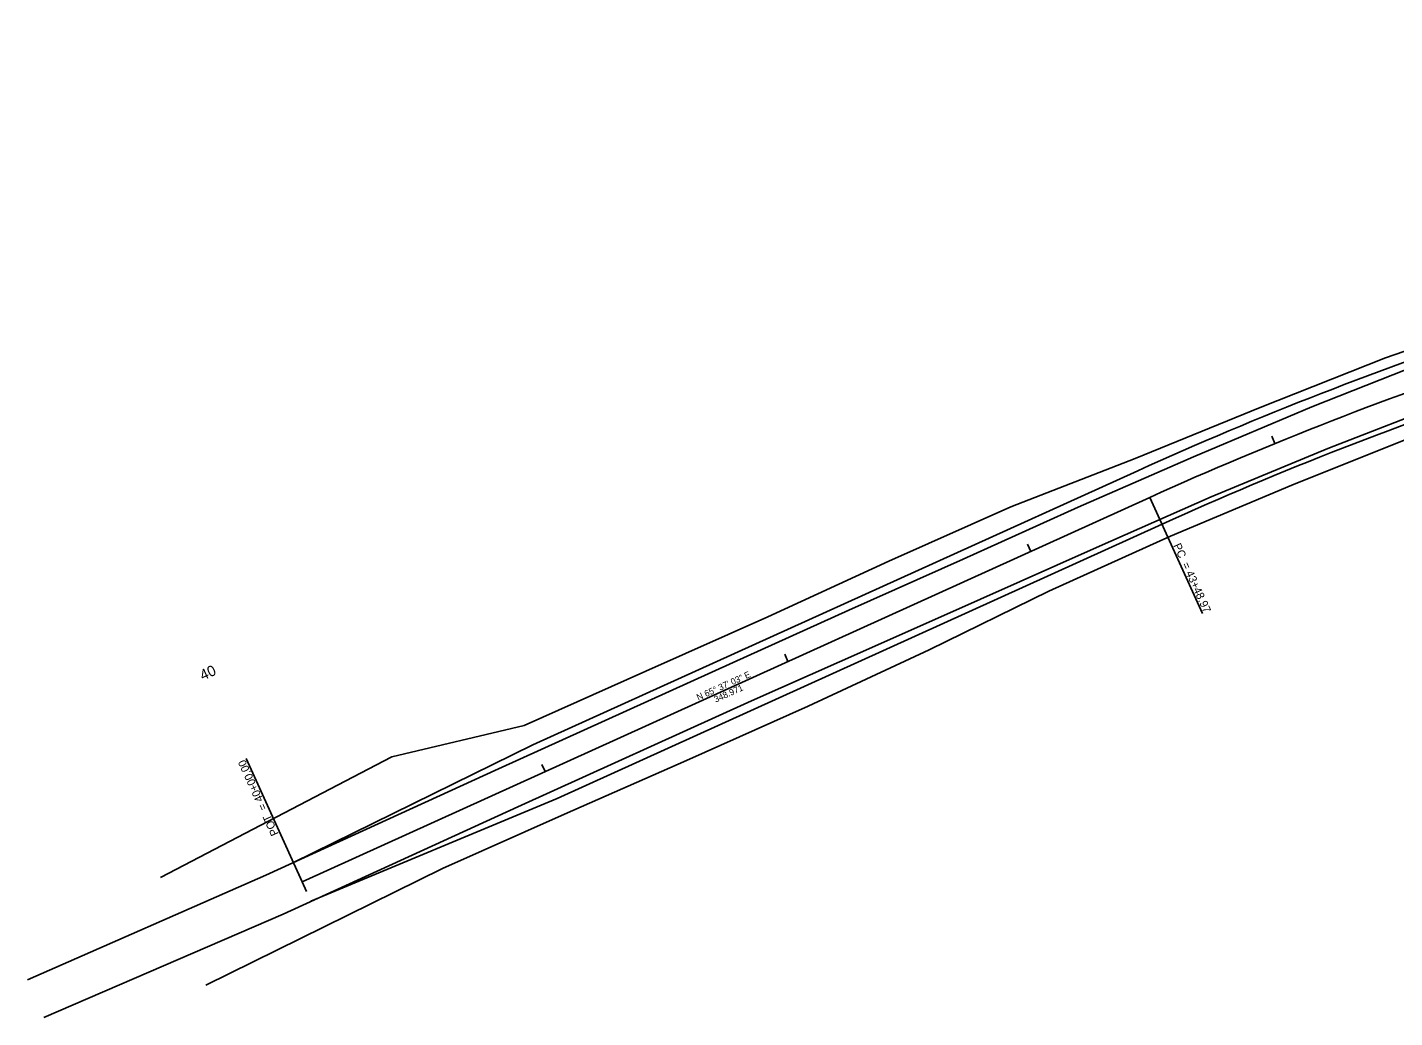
# Model space of a CAD drawing. Extents: x 1965724 to 1970316, y 1117080 to 1118173.
# Drawn here: x 1965724 to 1966236, y 1117080 to 1117451 of the extents above; entities that cross this region are included whole.
import ezdxf

# ---------------------------------------------------------------- set-up
doc = ezdxf.new("R2010")
doc.units = 0
for name, color, linetype in [('RD_EX_Road', 7, 'Continuous'), ('RD_EX_RW', 7, 'Continuous'), ('RD_HC_CL', 7, 'Continuous'), ('RD_HC_Data', 7, 'Continuous'), ('RD_HC_TX_Sta20', 7, 'Continuous'), ('RD_PD_Final_TrvlWay', 7, 'Continuous')]:
    doc.layers.add(name, color=color, linetype=linetype)

msp = doc.modelspace()

# ---------------------------------------------------------------- linework, layer by layer
at = {"layer": 'RD_EX_Road'}
for points in [[(1965723.84, 1117094.48), (1965813.3, 1117133.71), (1965900.46, 1117173.51), (1965988.47, 1117213.41), (1966031.82, 1117232.96), (1966074.66, 1117252.15), (1966117.78, 1117271.58), (1966161.06, 1117290.48), (1966205.41, 1117309.23), (1966251.25, 1117327.39), (1966297.25, 1117343.1), (1966344.08, 1117357.04), (1966390.78, 1117368.56), (1966438.12, 1117379.08), (1966484.55, 1117389.13), (1966531.2, 1117398.73), (1966578.39, 1117408.59), (1966604.53, 1117414.06), (1966624.54, 1117418.32), (1966671.32, 1117428.35), (1966716.51, 1117439.32), (1966736.6, 1117445.59), (1966754.13, 1117451.44)], [(1965729.99, 1117080.3), (1965819.77, 1117119.13), (1965907.74, 1117159.31), (1965995.36, 1117199.04), (1966039.27, 1117218.5), (1966081.24, 1117237.15), (1966124.67, 1117256.55), (1966167.66, 1117275.55), (1966211.47, 1117293.63), (1966257.79, 1117311.58), (1966302.7, 1117327.21), (1966347.9, 1117339.98), (1966394.81, 1117351.64), (1966441.56, 1117361.87), (1966488.62, 1117372.06), (1966534.91, 1117381.34), (1966581.23, 1117390.95), (1966629.53, 1117400.95), (1966675.63, 1117411.11), (1966721.68, 1117422.85), (1966766.8, 1117438.97), (1966775.75, 1117440.57)]]:
    msp.add_lwpolyline(points, dxfattribs=at)
at = {"layer": 'RD_EX_RW'}
for points in [[(1965790.81, 1117092.42), (1965879.47, 1117136.24), (1965925.17, 1117156.52), (1965970.94, 1117176.66), (1966016.61, 1117197.02), (1966061.92, 1117218.16), (1966106.86, 1117240.14), (1966152.39, 1117260.77), (1966197.92, 1117279.91), (1966243.77, 1117298.28), (1966290.04, 1117315.7), (1966337.21, 1117330.57), (1966385.03, 1117343.22), (1966433.37, 1117353.95), (1966482.26, 1117364.43), (1966531.37, 1117373.89), (1966580.17, 1117384.77), (1966628.88, 1117396.12), (1966677.82, 1117406.34), (1966728, 1117416.5), (1966777.64, 1117431.05)], [(1966139.22, 1117289.89), (1966186.05, 1117308.94), (1966233.02, 1117327.61), (1966280.8, 1117344.12), (1966329.24, 1117358.54), (1966377.84, 1117372.53)], [(1965773.8, 1117132.83), (1965860.52, 1117178.05), (1965910.11, 1117189.75), (1965955.74, 1117210.19), (1966001.44, 1117230.48), (1966046.84, 1117251.44), (1966092.54, 1117271.73), (1966139.22, 1117289.89)]]:
    msp.add_lwpolyline(points, dxfattribs=at)
at = {"layer": 'RD_HC_CL'}
msp.add_line((1965826.85, 1117131.21), (1966144.7, 1117275.28), dxfattribs=at)
msp.add_arc((1966705.48, 1116038.04), 1358.39, 101.90472, 114.38256, dxfattribs=at)
at = {"layer": 'RD_HC_Data'}
for p, q in [((1966191.56, 1117295.46), (1966190.42, 1117298.24)), ((1966144.7, 1117275.28), (1966164.43, 1117231.73)), ((1966100.09, 1117255.06), (1966098.86, 1117257.79)), ((1966009.01, 1117213.78), (1966007.77, 1117216.51)), ((1965826.85, 1117131.21), (1965805.9, 1117177.43)), ((1965917.93, 1117172.49), (1965916.69, 1117175.23)), ((1965826.85, 1117131.21), (1965825.2, 1117134.85)), ((1965826.85, 1117131.21), (1965828.5, 1117127.57))]:
    msp.add_line(p, q, dxfattribs=at)
at = {"layer": 'RD_PD_Final_TrvlWay'}
for p, q in [((1965913.39, 1117182.51), (1966140.16, 1117285.29)), ((1965922.47, 1117162.47), (1966149.24, 1117265.26)), ((1965823.59, 1117138.41), (1965913.39, 1117182.51)), ((1965830.17, 1117123.89), (1965922.47, 1117162.47))]:
    msp.add_line(p, q, dxfattribs=at)
for radius in [1369.39, 1347.39]:
    msp.add_arc((1966705.48, 1116038.04), radius, 101.90472, 114.38256, dxfattribs=at)

# ---------------------------------------------------------------- texts
at = {"layer": 'RD_HC_Data'}
for s, height, rotation, p in [('PC  = 43+48.97', 3, 294.3826, (1966153.41, 1117257.27)), ('N 65%%d 37\' 03" E', 2.4, 24.3826, (1965975.4, 1117199.09)), ('348.971', 2.4, 24.3826, (1965981.92, 1117198.31)), ('POT  = 40+00.00', 3, 114.3826, (1965818.14, 1117149.22))]:
    msp.add_text(s, height=height, rotation=rotation, dxfattribs=at).set_placement(p)
at = {"layer": 'RD_HC_TX_Sta20'}
msp.add_text('40', height=4, rotation=24.3826, dxfattribs=at).set_placement((1965789.61, 1117206.56))

doc.saveas('drawing.dxf')
